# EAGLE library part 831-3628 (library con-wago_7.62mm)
Serie 831, Stiftleiste (für Leiterplatten) mit abgewinkelten Einlötstiften / Series 831, Male header (for PCBs) with angled solder pins Polzahl / Pole No.: 8 Bemessungsspannung / Rated Voltage: 630 V Nennstrom / Nominal Current: 41 A Lötstiftlänge: / Solder Pin Length: 4 mm Farbe / Color: lichtgrau / light gray Stand: 01.01.2012. Die jeweils aktuellen Daten zu diesem Artikel finden Sie in unserem Produktkatalog, den Sie unter www.wago.com einsehen können. As of: 01/01/2012. Please find the newest data for this article in our product catalogue, which can be viewed under www.wago.com.
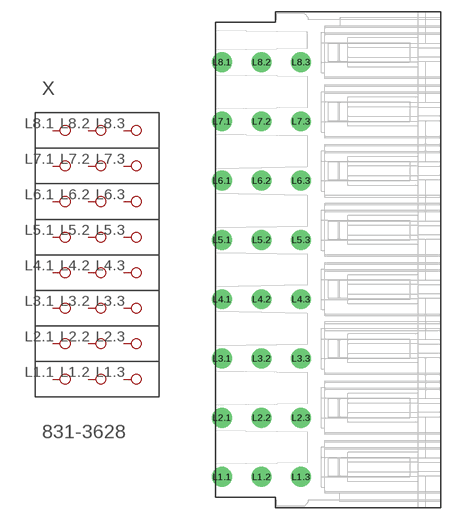
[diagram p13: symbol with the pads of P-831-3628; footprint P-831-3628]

Designator prefix X

## 831-3628  [P-831-3628]
L1.1  P1.1
L1.2  P1.2
L1.3  P1.3
L2.1  P2.1
L2.2  P2.2
L2.3  P2.3
L3.1  P3.1
L3.2  P3.2
L3.3  P3.3
L4.1  P4.1
L4.2  P4.2
L4.3  P4.3
L5.1  P5.1
L5.2  P5.2
L5.3  P5.3
L6.1  P6.1
L6.2  P6.2
L6.3  P6.3
L7.1  P7.1
L7.2  P7.2
L7.3  P7.3
L8.1  P8.1
L8.2  P8.2
L8.3  P8.3

## Footprint P-831-3628 (pad centres in mm)
drill 1.7 round: L1.1 -13.7,-27.94; L1.2 -8.62,-27.94; L1.3 -3.54,-27.94; L2.1 -13.7,-20.32; L2.2 -8.62,-20.32; L2.3 -3.54,-20.32; L3.1 -13.7,-12.7; L3.2 -8.62,-12.7; L3.3 -3.54,-12.7; L4.1 -13.7,-5.08; L4.2 -8.62,-5.08; L4.3 -3.54,-5.08; L5.1 -13.7,2.56; L5.2 -8.62,2.56; L5.3 -3.54,2.56; L6.1 -13.7,10.18; L6.2 -8.62,10.18; L6.3 -3.54,10.18; L7.1 -13.7,17.8; L7.2 -8.62,17.8; L7.3 -3.54,17.8; L8.1 -13.7,25.42; L8.2 -8.62,25.42; L8.3 -3.54,25.42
